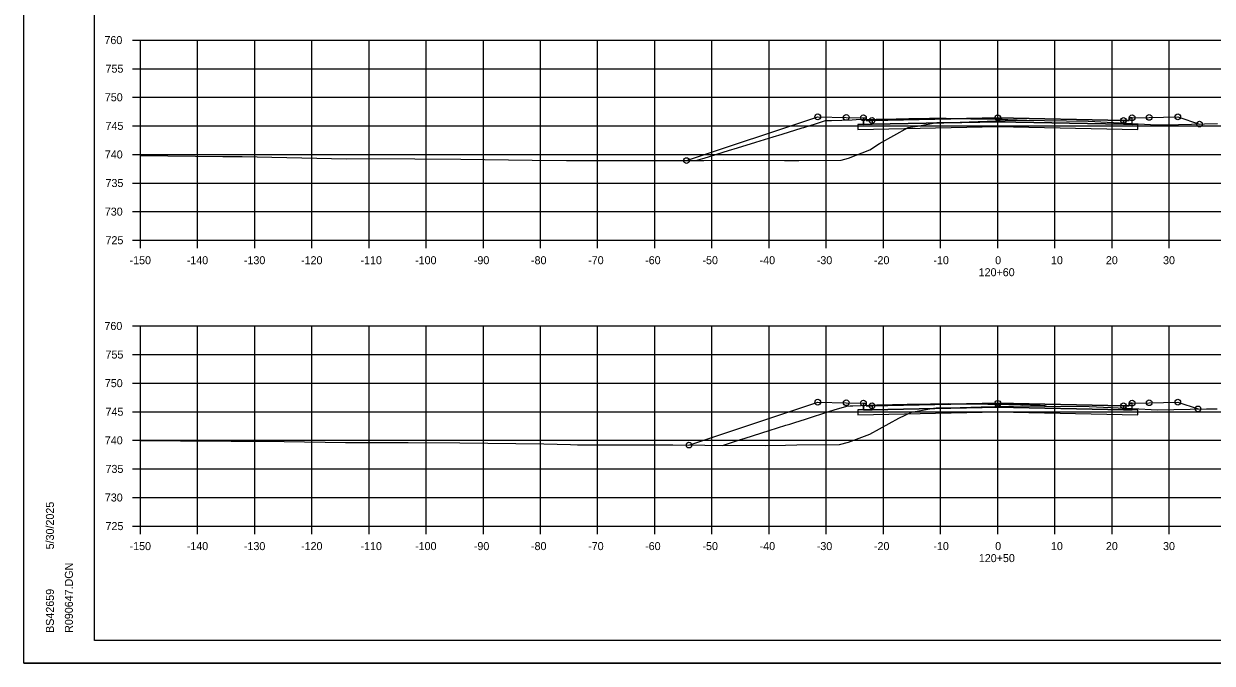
# Model space of a CAD drawing. Extents: x 1202951 to 1376887, y 378065 to 728038.
# Drawn here: x 1372926.7 to 1373134.7, y 380095.7 to 380207.6 of the extents above; entities that cross this region are included whole.
import ezdxf

# ---------------------------------------------------------------- set-up
doc = ezdxf.new("R2010")
doc.units = 0
for name, color, linetype in [('Default', 7, 'Continuous'), ('R_Alt Surface', 7, 'Continuous'), ('R_Axis', 7, 'Continuous'), ('R_Axis Annot', 7, 'Continuous'), ('R_Exist Surface', 7, 'Continuous'), ('R_Fin Surface', 7, 'Continuous'), ('R_Grid', 7, 'Continuous'), ('R_No Plot', 7, 'Continuous')]:
    doc.layers.add(name, color=color, linetype=linetype)

msp = doc.modelspace()

# ---------------------------------------------------------------- linework, layer by layer
at = {"layer": 'Default'}
for points in [[(1373073.63, 380191.15), (1373074.12, 380191.15), (1373074.13, 380190.65), (1373075.13, 380190.67), (1373075.13, 380190), (1373073.63, 380189.97)], [(1373120.63, 380191.15), (1373120.14, 380191.15), (1373120.13, 380190.65), (1373119.13, 380190.67), (1373119.13, 380190), (1373120.63, 380189.97)], [(1373073.63, 380141.24), (1373074.12, 380141.24), (1373074.13, 380140.74), (1373075.13, 380140.76), (1373075.13, 380140.09), (1373073.63, 380140.06)], [(1373120.63, 380141.24), (1373120.14, 380141.24), (1373120.13, 380140.74), (1373119.13, 380140.76), (1373119.13, 380140.09), (1373120.63, 380140.06)]]:
    msp.add_lwpolyline(points, close=True, dxfattribs=at)
at = {"layer": 'R_Alt Surface'}
for points in [[(1373073.63, 380191.15), (1373073.63, 380189.97), (1373075.13, 380190), (1373097.13, 380190.44), (1373119.13, 380190), (1373120.63, 380189.97), (1373120.63, 380191.15)], [(1373073.63, 380141.24), (1373073.63, 380140.06), (1373075.13, 380140.09), (1373097.13, 380140.53), (1373119.13, 380140.09), (1373120.63, 380140.06), (1373120.63, 380141.24)]]:
    msp.add_lwpolyline(points, dxfattribs=at)
for points in [[(1373075.13, 380190.67), (1373075.13, 380190), (1373097.13, 380190.44), (1373119.13, 380190), (1373119.13, 380190.67), (1373119.13, 380190.67), (1373097.13, 380191.11), (1373075.13, 380190.67)], [(1373097.13, 380190.44), (1373075.13, 380190), (1373073.63, 380189.97), (1373072.63, 380189.95), (1373072.63, 380189.12), (1373097.13, 380189.61), (1373121.63, 380189.12), (1373121.63, 380189.95), (1373120.63, 380189.97), (1373119.13, 380190)], [(1373075.13, 380140.76), (1373075.13, 380140.09), (1373097.13, 380140.53), (1373119.13, 380140.09), (1373119.13, 380140.76), (1373119.13, 380140.76), (1373097.13, 380141.2), (1373075.13, 380140.76)], [(1373097.13, 380140.53), (1373075.13, 380140.09), (1373073.63, 380140.06), (1373072.63, 380140.04), (1373072.63, 380139.21), (1373097.13, 380139.7), (1373121.63, 380139.21), (1373121.63, 380140.04), (1373120.63, 380140.06), (1373119.13, 380140.09)]]:
    msp.add_lwpolyline(points, close=True, dxfattribs=at)
at = {"layer": 'R_Axis'}
for p, q in [((1372945.73, 380204.73), (1372947.13, 380204.73)), ((1372947.13, 380169.73), (1372947.13, 380204.73)), ((1372945.73, 380199.73), (1372947.13, 380199.73)), ((1372945.73, 380194.73), (1372947.13, 380194.73)), ((1372945.73, 380189.73), (1372947.13, 380189.73)), ((1372945.73, 380184.73), (1372947.13, 380184.73)), ((1372945.73, 380179.73), (1372947.13, 380179.73)), ((1372945.73, 380174.73), (1372947.13, 380174.73)), ((1372945.73, 380169.73), (1372947.13, 380169.73)), ((1372947.13, 380169.73), (1373247.13, 380169.73)), ((1372947.13, 380168.33), (1372947.13, 380169.73)), ((1372957.13, 380168.33), (1372957.13, 380169.73)), ((1372967.13, 380168.33), (1372967.13, 380169.73)), ((1372977.13, 380168.33), (1372977.13, 380169.73)), ((1372987.13, 380168.33), (1372987.13, 380169.73)), ((1372997.13, 380168.33), (1372997.13, 380169.73)), ((1373007.13, 380168.33), (1373007.13, 380169.73)), ((1373017.13, 380168.33), (1373017.13, 380169.73)), ((1373027.13, 380168.33), (1373027.13, 380169.73)), ((1373037.13, 380168.33), (1373037.13, 380169.73)), ((1373047.13, 380168.33), (1373047.13, 380169.73)), ((1373057.13, 380168.33), (1373057.13, 380169.73)), ((1373067.13, 380168.33), (1373067.13, 380169.73)), ((1373077.13, 380168.33), (1373077.13, 380169.73)), ((1373087.13, 380168.33), (1373087.13, 380169.73)), ((1373097.13, 380168.33), (1373097.13, 380169.73)), ((1373107.13, 380168.33), (1373107.13, 380169.73)), ((1373117.13, 380168.33), (1373117.13, 380169.73)), ((1373127.13, 380168.33), (1373127.13, 380169.73)), ((1372945.73, 380154.73), (1372947.13, 380154.73)), ((1372947.13, 380119.73), (1372947.13, 380154.73)), ((1372945.73, 380149.73), (1372947.13, 380149.73)), ((1372945.73, 380144.73), (1372947.13, 380144.73)), ((1372945.73, 380139.73), (1372947.13, 380139.73)), ((1372945.73, 380134.73), (1372947.13, 380134.73)), ((1372945.73, 380129.73), (1372947.13, 380129.73)), ((1372945.73, 380124.73), (1372947.13, 380124.73)), ((1372945.73, 380119.73), (1372947.13, 380119.73)), ((1372947.13, 380119.73), (1373247.13, 380119.73)), ((1372947.13, 380118.33), (1372947.13, 380119.73)), ((1372957.13, 380118.33), (1372957.13, 380119.73)), ((1372967.13, 380118.33), (1372967.13, 380119.73)), ((1372977.13, 380118.33), (1372977.13, 380119.73)), ((1372987.13, 380118.33), (1372987.13, 380119.73)), ((1372997.13, 380118.33), (1372997.13, 380119.73)), ((1373007.13, 380118.33), (1373007.13, 380119.73)), ((1373017.13, 380118.33), (1373017.13, 380119.73)), ((1373027.13, 380118.33), (1373027.13, 380119.73)), ((1373037.13, 380118.33), (1373037.13, 380119.73)), ((1373047.13, 380118.33), (1373047.13, 380119.73)), ((1373057.13, 380118.33), (1373057.13, 380119.73)), ((1373067.13, 380118.33), (1373067.13, 380119.73)), ((1373077.13, 380118.33), (1373077.13, 380119.73)), ((1373087.13, 380118.33), (1373087.13, 380119.73)), ((1373097.13, 380118.33), (1373097.13, 380119.73)), ((1373107.13, 380118.33), (1373107.13, 380119.73)), ((1373117.13, 380118.33), (1373117.13, 380119.73)), ((1373127.13, 380118.33), (1373127.13, 380119.73))]:
    msp.add_line(p, q, dxfattribs=at)
at = {"layer": 'R_Exist Surface'}
for points in [[(1372947.13, 380184.52), (1372961.54, 380184.38), (1372963.19, 380184.38), (1372964.93, 380184.36), (1372983.19, 380183.99), (1372987.12, 380184), (1373003.2, 380183.91), (1373015.66, 380183.74), (1373021.68, 380183.66), (1373023.42, 380183.68), (1373028.94, 380183.66), (1373045.68, 380183.65), (1373049.22, 380183.7), (1373059.83, 380183.68), (1373062.31, 380183.67), (1373069.76, 380183.71), (1373071.01, 380184.1), (1373074.73, 380185.54), (1373076.44, 380186.67), (1373081.46, 380189.45), (1373083.09, 380189.68), (1373086.46, 380190.34), (1373090.53, 380190.38), (1373090.56, 380190.38), (1373100, 380190.7), (1373101.36, 380190.75), (1373101.48, 380190.75), (1373101.49, 380190.75), (1373112.94, 380190.54), (1373112.99, 380190.53), (1373124.96, 380189.88), (1373128.78, 380189.96), (1373135.58, 380190.12)], [(1373042.67, 380183.65), (1373065.63, 380191.31), (1373070.63, 380191.21), (1373073.63, 380191.15), (1373074.12, 380191.15), (1373074.13, 380190.65), (1373075.13, 380190.67), (1373097.13, 380191.11), (1373119.13, 380190.67), (1373120.13, 380190.65), (1373120.14, 380191.15), (1373120.63, 380191.15), (1373123.63, 380191.21), (1373128.63, 380191.31), (1373132.42, 380190.04)], [(1373044.28, 380183.65), (1373045.54, 380184.03), (1373045.76, 380184.1), (1373050.01, 380185.4), (1373051.6, 380185.89), (1373054.78, 380186.87), (1373057.83, 380187.81), (1373059.41, 380188.3), (1373062.94, 380189.39), (1373063.18, 380189.46), (1373064.5, 380189.87), (1373065.04, 380190.04), (1373066.97, 380190.64), (1373067.57, 380190.65), (1373068.05, 380190.65), (1373071.66, 380190.79), (1373072.36, 380190.82), (1373079.36, 380190.97), (1373081.56, 380191.02), (1373085.19, 380191.09), (1373086.65, 380191.07), (1373087.69, 380191.05), (1373088.11, 380191.05), (1373089.47, 380191.03), (1373092.44, 380190.98), (1373096.71, 380190.91), (1373097.93, 380190.89), (1373098.88, 380190.86), (1373102.15, 380190.74), (1373102.19, 380190.73)], [(1372947.13, 380134.69), (1372954.15, 380134.62), (1372962.99, 380134.61), (1372972.3, 380134.55), (1372983, 380134.33), (1372993.95, 380134.34), (1373003, 380134.3), (1373017.7, 380134.09), (1373022.36, 380134.01), (1373023.59, 380133.93), (1373040.26, 380133.92), (1373045.86, 380133.86), (1373056.47, 380133.84), (1373060.01, 380133.86), (1373061.96, 380133.95), (1373069.43, 380134), (1373071.04, 380134.38), (1373074.77, 380135.82), (1373079.82, 380138.61), (1373082.02, 380139.65), (1373085.87, 380140.38), (1373086.35, 380140.44), (1373087.71, 380140.44), (1373090.57, 380140.46), (1373094.24, 380140.59), (1373101.44, 380140.77), (1373101.48, 380140.77), (1373105.32, 380140.7), (1373113.11, 380140.66), (1373120.69, 380140.28), (1373125.1, 380140.05), (1373133.65, 380140.26), (1373135.54, 380140.24)], [(1373043.11, 380133.89), (1373065.63, 380141.4), (1373070.63, 380141.3), (1373073.63, 380141.24), (1373074.12, 380141.24), (1373074.13, 380140.74), (1373075.13, 380140.76), (1373097.13, 380141.2), (1373119.13, 380140.76), (1373120.13, 380140.74), (1373120.14, 380141.24), (1373120.63, 380141.24), (1373123.63, 380141.3), (1373128.63, 380141.4), (1373132.17, 380140.22)], [(1373048.96, 380133.85), (1373051.94, 380134.79), (1373052.96, 380135.11), (1373057.14, 380136.43), (1373060.07, 380137.36), (1373060.73, 380137.57), (1373061.6, 380137.84), (1373063.47, 380138.43), (1373067.78, 380139.8), (1373068.52, 380140.04), (1373070.7, 380140.73), (1373071.3, 380140.74), (1373071.75, 380140.74), (1373073.19, 380140.8), (1373075.97, 380140.91), (1373076.17, 380140.92), (1373081.26, 380141.03), (1373085.34, 380141.12), (1373088.57, 380141.19), (1373091.63, 380141.14), (1373093.77, 380141.11), (1373095.4, 380141.08), (1373101.09, 380140.99), (1373104.54, 380140.86), (1373105.25, 380140.84), (1373105.29, 380140.83), (1373105.68, 380140.7)]]:
    msp.add_lwpolyline(points, dxfattribs=at)
at = {"layer": 'R_Fin Surface'}
for points in [[(1373065.63, 380191.31), (1373070.63, 380191.21), (1373073.63, 380191.15), (1373074.12, 380191.15), (1373074.13, 380190.65), (1373075.13, 380190.67), (1373075.13, 380190.67), (1373097.13, 380191.11), (1373119.13, 380190.67), (1373119.13, 380190.67), (1373120.13, 380190.65), (1373120.14, 380191.15), (1373120.63, 380191.15), (1373123.63, 380191.21), (1373128.63, 380191.31)], [(1373065.63, 380141.4), (1373070.63, 380141.3), (1373073.63, 380141.24), (1373074.12, 380141.24), (1373074.13, 380140.74), (1373075.13, 380140.76), (1373075.13, 380140.76), (1373097.13, 380141.2), (1373119.13, 380140.76), (1373119.13, 380140.76), (1373120.13, 380140.74), (1373120.14, 380141.24), (1373120.63, 380141.24), (1373123.63, 380141.3), (1373128.63, 380141.4)]]:
    msp.add_lwpolyline(points, dxfattribs=at)
at = {"layer": 'R_Grid'}
for p, q in [((1372947.13, 380204.73), (1373247.13, 380204.73)), ((1372947.13, 380169.73), (1372947.13, 380204.73)), ((1372957.13, 380169.73), (1372957.13, 380204.73)), ((1372967.13, 380169.73), (1372967.13, 380204.73)), ((1372977.13, 380169.73), (1372977.13, 380204.73)), ((1372987.13, 380169.73), (1372987.13, 380204.73)), ((1372997.13, 380169.73), (1372997.13, 380204.73)), ((1373007.13, 380169.73), (1373007.13, 380204.73)), ((1373017.13, 380169.73), (1373017.13, 380204.73)), ((1373027.13, 380169.73), (1373027.13, 380204.73)), ((1373037.13, 380169.73), (1373037.13, 380204.73)), ((1373047.13, 380169.73), (1373047.13, 380204.73)), ((1373057.13, 380169.73), (1373057.13, 380204.73)), ((1373067.13, 380169.73), (1373067.13, 380204.73)), ((1373077.13, 380169.73), (1373077.13, 380204.73)), ((1373087.13, 380169.73), (1373087.13, 380204.73)), ((1373097.13, 380169.73), (1373097.13, 380204.73)), ((1373107.13, 380169.73), (1373107.13, 380204.73)), ((1373117.13, 380169.73), (1373117.13, 380204.73)), ((1373127.13, 380169.73), (1373127.13, 380204.73)), ((1372947.13, 380199.73), (1373247.13, 380199.73)), ((1372947.13, 380194.73), (1373247.13, 380194.73)), ((1372947.13, 380189.73), (1373247.13, 380189.73)), ((1372947.13, 380184.73), (1373247.13, 380184.73)), ((1372947.13, 380179.73), (1373247.13, 380179.73)), ((1372947.13, 380174.73), (1373247.13, 380174.73)), ((1372947.13, 380169.73), (1373247.13, 380169.73)), ((1372947.13, 380154.73), (1373247.13, 380154.73)), ((1372947.13, 380119.73), (1372947.13, 380154.73)), ((1372957.13, 380119.73), (1372957.13, 380154.73)), ((1372967.13, 380119.73), (1372967.13, 380154.73)), ((1372977.13, 380119.73), (1372977.13, 380154.73)), ((1372987.13, 380119.73), (1372987.13, 380154.73)), ((1372997.13, 380119.73), (1372997.13, 380154.73)), ((1373007.13, 380119.73), (1373007.13, 380154.73)), ((1373017.13, 380119.73), (1373017.13, 380154.73)), ((1373027.13, 380119.73), (1373027.13, 380154.73)), ((1373037.13, 380119.73), (1373037.13, 380154.73)), ((1373047.13, 380119.73), (1373047.13, 380154.73)), ((1373057.13, 380119.73), (1373057.13, 380154.73)), ((1373067.13, 380119.73), (1373067.13, 380154.73)), ((1373077.13, 380119.73), (1373077.13, 380154.73)), ((1373087.13, 380119.73), (1373087.13, 380154.73)), ((1373097.13, 380119.73), (1373097.13, 380154.73)), ((1373107.13, 380119.73), (1373107.13, 380154.73)), ((1373117.13, 380119.73), (1373117.13, 380154.73)), ((1373127.13, 380119.73), (1373127.13, 380154.73)), ((1372947.13, 380149.73), (1373247.13, 380149.73)), ((1372947.13, 380144.73), (1373247.13, 380144.73)), ((1372947.13, 380139.73), (1373247.13, 380139.73)), ((1372947.13, 380134.73), (1373247.13, 380134.73)), ((1372947.13, 380129.73), (1373247.13, 380129.73)), ((1372947.13, 380124.73), (1373247.13, 380124.73)), ((1372947.13, 380119.73), (1373247.13, 380119.73))]:
    msp.add_line(p, q, dxfattribs=at)
at = {"layer": 'R_No Plot'}
for p, q in [((1372939.13, 380099.73), (1372939.13, 380305.19)), ((1372939.13, 380099.73), (1372939.13, 380099.73)), ((1373255.31, 380099.73), (1372939.13, 380099.73)), ((1372926.73, 380095.75), (1373260.07, 380095.75))]:
    msp.add_line(p, q, dxfattribs=at)
for points in [[(1372926.73, 380309.08), (1373260.07, 380309.08), (1373260.07, 380095.75), (1372926.73, 380095.75)], [(1373173.05, 380305.19), (1373192.67, 380305.19), (1373192.67, 380295.31), (1373208.79, 380295.31), (1373231.99, 380295.31), (1373231.99, 380270.98), (1373255.31, 380270.98), (1373255.31, 380099.73), (1372939.13, 380099.73), (1372939.13, 380305.19)]]:
    msp.add_lwpolyline(points, close=True, dxfattribs=at)
for centre in [(1373065.63, 380191.31), (1373070.63, 380191.21), (1373073.63, 380191.15), (1373075.13, 380190.67), (1373097.13, 380191.11), (1373119.13, 380190.67), (1373120.63, 380191.15), (1373123.63, 380191.21), (1373128.63, 380191.31), (1373132.42, 380190.04), (1373042.67, 380183.65), (1373065.63, 380141.4), (1373070.63, 380141.3), (1373073.63, 380141.24), (1373075.13, 380140.76), (1373097.13, 380141.2), (1373119.13, 380140.76), (1373120.63, 380141.24), (1373123.63, 380141.3), (1373128.63, 380141.4), (1373132.17, 380140.22), (1373043.11, 380133.89)]:
    msp.add_circle(centre, 0.5, dxfattribs=at)

# ---------------------------------------------------------------- texts
at = {"layer": 'R_Axis Annot'}
for s, p in [('760', (1372940.84, 380204.03)), ('755', (1372941.03, 380199.03)), ('750', (1372940.91, 380194.03)), ('745', (1372941.03, 380189.03)), ('740', (1372940.91, 380184.03)), ('735', (1372941.03, 380179.03)), ('730', (1372940.91, 380174.03)), ('725', (1372941.03, 380169.03)), ('-150', (1372945.24, 380165.53)), ('-140', (1372955.24, 380165.53)), ('-130', (1372965.24, 380165.53)), ('-120', (1372975.24, 380165.53)), ('-110', (1372985.64, 380165.53)), ('-100', (1372995.19, 380165.53)), ('-90', (1373005.47, 380165.53)), ('-80', (1373015.47, 380165.53)), ('-70', (1373025.47, 380165.53)), ('-60', (1373035.44, 380165.53)), ('-50', (1373045.47, 380165.53)), ('-40', (1373055.47, 380165.53)), ('-30', (1373065.47, 380165.53)), ('-20', (1373075.47, 380165.53)), ('-10', (1373085.87, 380165.53)), ('0', (1373096.68, 380165.53)), ('10', (1373106.44, 380165.53)), ('20', (1373116.05, 380165.53)), ('30', (1373126.05, 380165.53)), ('120+60', (1373093.79, 380163.43)), ('760', (1372940.84, 380154.03)), ('755', (1372941.03, 380149.03)), ('750', (1372940.91, 380144.03)), ('745', (1372941.03, 380139.03)), ('740', (1372940.91, 380134.03)), ('735', (1372941.03, 380129.03)), ('730', (1372940.91, 380124.03)), ('725', (1372941.03, 380119.03)), ('-150', (1372945.24, 380115.53)), ('-140', (1372955.24, 380115.53)), ('-130', (1372965.24, 380115.53)), ('-120', (1372975.24, 380115.53)), ('-110', (1372985.64, 380115.53)), ('-100', (1372995.19, 380115.53)), ('-90', (1373005.47, 380115.53)), ('-80', (1373015.47, 380115.53)), ('-70', (1373025.47, 380115.53)), ('-60', (1373035.44, 380115.53)), ('-50', (1373045.47, 380115.53)), ('-40', (1373055.47, 380115.53)), ('-30', (1373065.47, 380115.53)), ('-20', (1373075.47, 380115.53)), ('-10', (1373085.87, 380115.53)), ('0', (1373096.68, 380115.53)), ('10', (1373106.44, 380115.53)), ('20', (1373116.05, 380115.53)), ('30', (1373126.05, 380115.53)), ('120+50', (1373093.82, 380113.43))]:
    msp.add_text(s, height=1.4, dxfattribs=at).set_placement(p)
at = {"layer": 'R_No Plot'}
for s, p in [('5/30/2025', (1372932, 380115.66)), ('R090647.DGN', (1372935.32, 380101.05)), ('BS42659', (1372932, 380101.05))]:
    msp.add_text(s, height=1.4, rotation=90, dxfattribs=at).set_placement(p)

doc.saveas('drawing.dxf')
